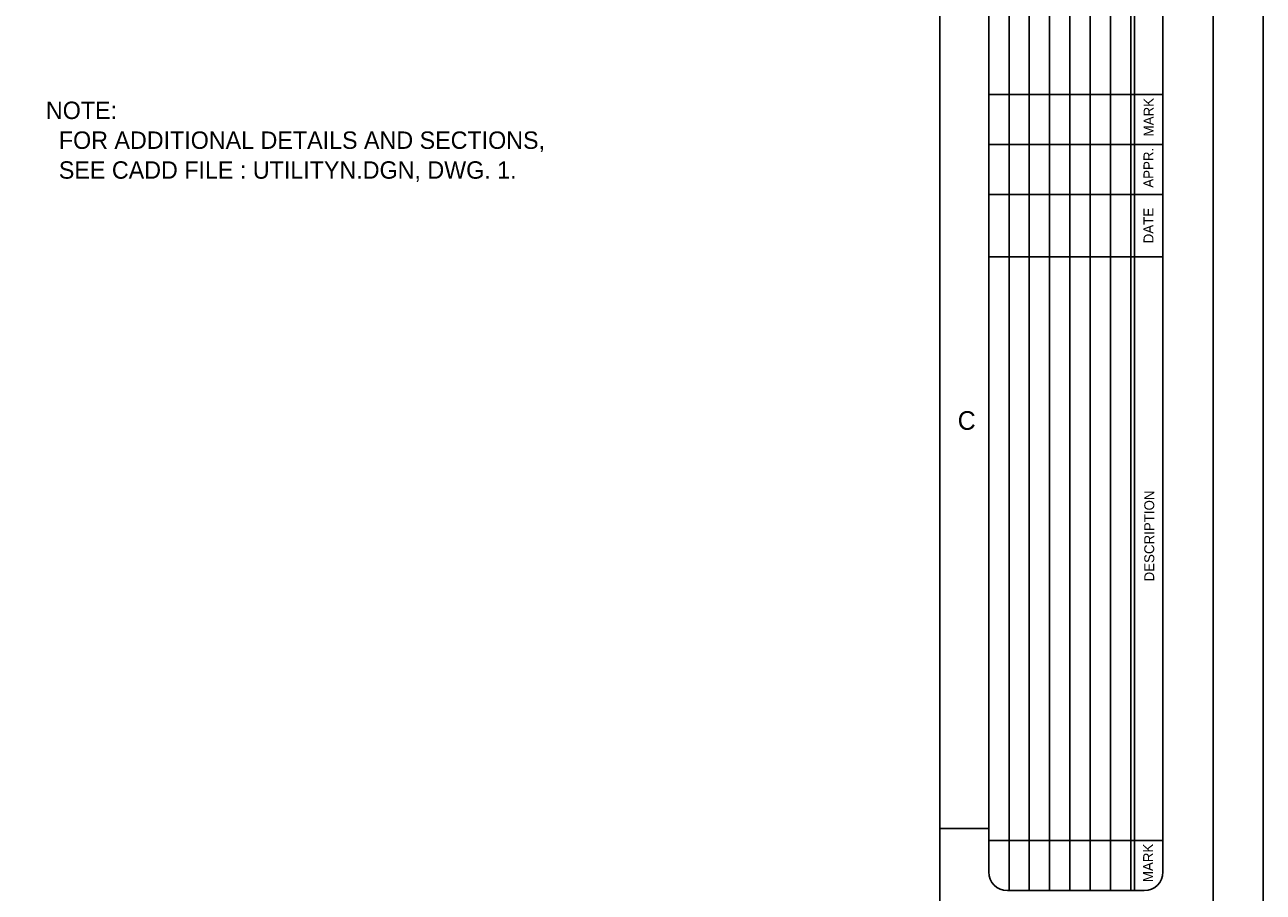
# Model space of a CAD drawing. Extents: x 22388.1 to 22405.7, y 22369.6 to 22390.4.
# Drawn here: x 22398.639 to 22402.79, y 22375.068 to 22377.974 of the extents above; entities that cross this region are included whole.
import ezdxf

# ---------------------------------------------------------------- set-up
doc = ezdxf.new("R2010")
doc.units = 0
for name, color, linetype in [('Level 1', 7, 'Continuous'), ('Level 10', 7, 'Continuous'), ('Level 7', 7, 'Continuous'), ('Level 9', 7, 'Continuous')]:
    doc.layers.add(name, color=color, linetype=linetype)

msp = doc.modelspace()

# ---------------------------------------------------------------- linework, layer by layer
at = {"layer": 'Level 1'}
for p, q in [((22401.9379, 22380.073), (22401.9379, 22375.073)), ((22402.0059, 22380.073), (22402.0059, 22375.073)), ((22402.0739, 22380.073), (22402.0739, 22375.073)), ((22402.1419, 22380.073), (22402.1419, 22375.073)), ((22402.2099, 22380.073), (22402.2099, 22375.073)), ((22402.2779, 22380.073), (22402.2779, 22375.073)), ((22402.3459, 22380.073), (22402.3459, 22375.073)), ((22402.3579, 22380.073), (22402.3579, 22375.073)), ((22402.4539, 22377.573), (22401.8699, 22377.573)), ((22402.3914, 22375.073), (22401.9324, 22375.073))]:
    msp.add_line(p, q, dxfattribs=at)
msp.add_lwpolyline([(22388.1232, 22380.9477), (22402.7899, 22380.9477), (22402.7899, 22369.6143), (22388.1232, 22369.6143)], close=True, dxfattribs=at)
for points in [[(22401.8699, 22375.1355), (22401.8699, 22380.0105)], [(22402.4539, 22375.1355), (22402.4539, 22380.0105)]]:
    msp.add_lwpolyline(points, dxfattribs=at)
for centre, start, end in [((22401.9324, 22375.1355), 180, 270), ((22402.3914, 22375.1355), 270, 0)]:
    msp.add_arc(centre, 0.0625, start, end, dxfattribs=at)
at = {"layer": 'Level 10'}
msp.add_line((22401.7059, 22375.281), (22401.8699, 22375.281), dxfattribs=at)
at = {"layer": 'Level 7'}
for p, q in [((22402.4539, 22377.405), (22401.8699, 22377.405)), ((22402.4539, 22377.1967), (22401.8699, 22377.1967)), ((22402.4539, 22375.241), (22401.8699, 22375.241))]:
    msp.add_line(p, q, dxfattribs=at)
msp.add_lwpolyline([(22402.4539, 22377.741), (22401.8699, 22377.741)], dxfattribs=at)
at = {"layer": 'Level 9'}
msp.add_line((22402.6219, 22369.781), (22402.6219, 22380.781), dxfattribs=at)
msp.add_lwpolyline([(22401.7059, 22369.781), (22401.7059, 22380.781)], dxfattribs=at)

# ---------------------------------------------------------------- texts
at = {"layer": 'Level 1'}
for s, height, p in [('MARK', 0.03333, (22402.4226, 22377.6002)), ('APPR.', 0.03333, (22402.4219, 22377.4282)), ('DATE', 0.03333, (22402.4219, 22377.242)), ('DESCRIPTION', 0.033333, (22402.4246, 22376.109)), ('MARK', 0.03333, (22402.4208, 22375.1014))]:
    msp.add_text(s, height=height, rotation=90, dxfattribs=at).set_placement(p)
msp.add_text('C', height=0.0624, dxfattribs=at).set_placement((22401.7659, 22376.617))
at = {"layer": 'Level 10'}
for s, height, p in [('NOTE:', 0.05833, (22398.7096, 22377.6584)), ('  FOR ADDITIONAL DETAILS AND SECTIONS,', 0.058333, (22398.7096, 22377.5584)), ('  SEE CADD FILE : UTILITYN.DGN, DWG. 1.', 0.058333, (22398.7096, 22377.4584))]:
    msp.add_text(s, height=height, dxfattribs=at).set_placement(p)

doc.saveas('drawing.dxf')
